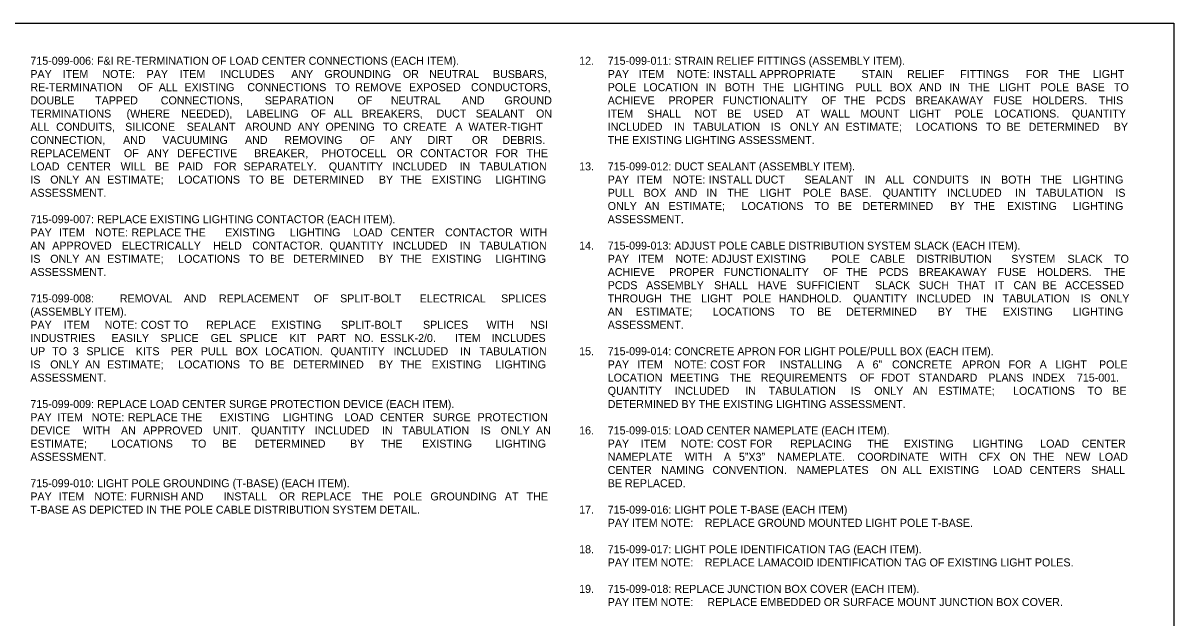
# Model space of a CAD drawing. Extents: x -55 to 2471539, y -90 to 3608906.
# Drawn here: x 543 to 1540, y 445 to 960 of the extents above; entities that cross this region are included whole.
import ezdxf

# ---------------------------------------------------------------- set-up
doc = ezdxf.new("R2010")
doc.units = 0
doc.layers.add('NonPlottingEle_dp', color=7, linetype='Continuous')
doc.layers.add('TextNotes', color=7, linetype='Continuous')

msp = doc.modelspace()

# ---------------------------------------------------------------- linework, layer by layer
at = {"layer": 'NonPlottingEle_dp'}
msp.add_lwpolyline([(0, 0), (0, 960), (1540, 960), (1540, 0)], dxfattribs=at)

# ---------------------------------------------------------------- texts
at = {"layer": 'TextNotes'}
for s, p in [('715-099-006: F&I RE-TERMINATION OF LOAD CENTER CONNECTIONS (EACH ITEM).', (549.7, 923.83)), ('12.', (1024.92, 923.83)), ('715-099-011: STRAIN RELIEF FITTINGS (ASSEMBLY ITEM).', (1049.65, 923.83)), ('PAY ', (549.7, 912.39)), ('ITEM ', (577.74, 912.39)), ('NOTE: ', (612.1, 912.39)), ('PAY ', (650.39, 912.39)), ('ITEM ', (679.08, 912.39)), ('INCLUDES ', (714.25, 912.39)), ('ANY ', (775.58, 912.39)), ('GROUNDING ', (804.34, 912.39)), ('OR ', (872.29, 912.39)), ('NEUTRAL ', (895.07, 912.39)), ('BUSBARS, ', (950.28, 912.39)), ('PAY ', (1049.65, 912.39)), ('ITEM ', (1076.47, 912.39)), ('NOTE:', (1109.6, 912.39)), (' INSTALL APPROPRIATE ', (1138.35, 912.39)), ('STAIN ', (1269.39, 912.39)), ('RELIEF ', (1308.85, 912.39)), ('FITTINGS ', (1354.86, 912.39)), ('FOR ', (1411.77, 912.39)), ('THE ', (1439.97, 912.39)), ('LIGHT ', (1469.78, 912.39)), ('RE-TERMINATION ', (549.7, 900.96)), ('OF ', (643.08, 900.96)), ('ALL ', (660.93, 900.96)), ('EXISTING ', (683.15, 900.96)), ('CONNECTIONS ', (737.56, 900.96)), ('TO ', (813.52, 900.96)), ('REMOVE ', (831.03, 900.96)), ('EXPOSED ', (877.57, 900.96)), ('CONDUCTORS, ', (931.26, 900.96)), ('POLE ', (1049.65, 900.96)), ('LOCATION ', (1080.56, 900.96)), ('IN ', (1134.43, 900.96)), ('BOTH ', (1151.04, 900.96)), ('THE ', (1183.91, 900.96)), ('LIGHTING ', (1210.53, 900.96)), ('PULL ', (1264.1, 900.96)), ('BOX ', (1293.78, 900.96)), ('AND ', (1319.3, 900.96)), ('IN ', (1345.38, 900.96)), ('THE ', (1361.99, 900.96)), ('LIGHT ', (1388.61, 900.96)), ('POLE ', (1424.48, 900.96)), ('BASE ', (1455.39, 900.96)), ('TO ', (1488.08, 900.96)), ('DOUBLE ', (549.7, 889.52)), ('TAPPED ', (605.77, 889.52)), ('CONNECTIONS, ', (662.65, 889.52)), ('SEPARATION ', (752.7, 889.52)), ('OF ', (833, 889.52)), ('NEUTRAL ', (861.91, 889.52)), ('AND ', (923.39, 889.52)), ('GROUND ', (960.17, 889.52)), ('ACHIEVE ', (1049.65, 889.52)), ('PROPER ', (1102.26, 889.52)), ('FUNCTIONALITY ', (1149.23, 889.52)), ('OF ', (1234.77, 889.52)), ('THE ', (1254.12, 889.52)), ('PCDS ', (1281.88, 889.52)), ('BREAKAWAY ', (1316.19, 889.52)), ('FUSE ', (1383.74, 889.52)), ('HOLDERS. ', (1417.5, 889.52)), ('THIS ', (1474.9, 889.52)), ('TERMINATIONS ', (549.7, 878.09)), ('(WHERE ', (633, 878.09)), ('NEEDED), ', (680.31, 878.09)), ('LABELING ', (736.72, 878.09)), ('OF ', (792.62, 878.09)), ('ALL ', (812.36, 878.09)), ('BREAKERS, ', (836.49, 878.09)), ('DUCT ', (901.5, 878.09)), ('SEALANT ', (935.34, 878.09)), ('ON ', (987.58, 878.09)), ('ITEM ', (1049.65, 878.09)), ('SHALL ', (1083.84, 878.09)), ('NOT ', (1124.85, 878.09)), ('BE ', (1153.02, 878.09)), ('USED ', (1175.78, 878.09)), ('AT ', (1212.78, 878.09)), ('WALL ', (1234.12, 878.09)), ('MOUNT ', (1268.41, 878.09)), ('LIGHT ', (1310.87, 878.09)), ('POLE ', (1350.18, 878.09)), ('LOCATIONS. ', (1384.52, 878.09)), ('QUANTITY ', (1451.55, 878.09)), ('ALL ', (549.7, 866.65)), ('CONDUITS, ', (572.05, 866.65)), ('SILICONE ', (631.83, 866.65)), ('SEALANT ', (685.05, 866.65)), ('AROUND ', (735.51, 866.65)), ('ANY ', (781.11, 866.65)), ('OPENING ', (805.22, 866.65)), ('TO ', (854.97, 866.65)), ('CREATE ', (872.61, 866.65)), ('A ', (917.72, 866.65)), ('WATER-TIGHT ', (929.09, 866.65)), ('INCLUDED ', (1049.65, 866.65)), ('IN ', (1107.05, 866.65)), ('TABULATION ', (1123.54, 866.65)), ('IS ', (1190.8, 866.65)), ('ONLY ', (1207.43, 866.65)), ('AN ', (1237.1, 866.65)), ('ESTIMATE; ', (1255.46, 866.65)), ('LOCATIONS ', (1316.43, 866.65)), ('TO ', (1377.19, 866.65)), ('BE ', (1394.94, 866.65)), ('DETERMINED ', (1414.15, 866.65)), ('BY ', (1487.82, 866.65)), ('CONNECTION, ', (549.7, 855.22)), ('AND ', (630.03, 855.22)), ('VACUUMING ', (664.09, 855.22)), ('AND ', (735.55, 855.22)), ('REMOVING ', (769.61, 855.22)), ('OF ', (835.13, 855.22)), ('ANY ', (861.32, 855.22)), ('DIRT ', (893.64, 855.22)), ('OR ', (932.08, 855.22)), ('DEBRIS. ', (958.43, 855.22)), ('THE EXISTING LIGHTING ASSESSMENT.', (1049.65, 855.22)), ('REPLACEMENT ', (549.7, 843.78)), ('OF ', (630.73, 843.78)), ('ANY ', (650.75, 843.78)), ('DEFECTIVE ', (676.9, 843.78)), ('BREAKER, ', (743.47, 843.78)), ('PHOTOCELL ', (801.75, 843.78)), ('OR ', (867.07, 843.78)), ('CONTACTOR ', (887.24, 843.78)), ('FOR ', (952.56, 843.78)), ('THE ', (979.39, 843.78)), ('LOAD ', (549.7, 832.35)), ('CENTER ', (581.37, 832.35)), ('WILL ', (627.9, 832.35)), ('BE ', (657.55, 832.35)), ('PAID ', (677.54, 832.35)), ('FOR ', (708.69, 832.35)), ('SEPARATELY. ', (734.37, 832.35)), ('QUANTITY ', (808.13, 832.35)), ('INCLUDED ', (863.18, 832.35)), ('IN ', (921.36, 832.35)), ('TABULATION ', (938.63, 832.35)), ('13.', (1024.92, 832.35)), ('715-099-012: DUCT SEALANT (ASSEMBLY ITEM).', (1049.65, 832.35)), ('IS ', (549.7, 820.92)), ('ONLY ', (566.92, 820.92)), ('AN ', (597.19, 820.92)), ('ESTIMATE; ', (616.14, 820.92)), ('LOCATIONS ', (677.71, 820.92)), ('TO ', (739.06, 820.92)), ('BE ', (757.41, 820.92)), ('DETERMINED ', (777.21, 820.92)), ('BY ', (851.47, 820.92)), ('THE ', (870.08, 820.92)), ('EXISTING ', (897.18, 820.92)), ('LIGHTING ', (952.43, 820.92)), ('PAY ', (1049.65, 820.92)), ('ITEM ', (1074.62, 820.92)), ('NOTE:', (1105.9, 820.92)), (' INSTALL DUCT ', (1134.65, 820.92)), ('SEALANT ', (1220.03, 820.92)), ('IN ', (1272.07, 820.92)), ('ALL ', (1290.01, 820.92)), ('CONDUITS ', (1313.94, 820.92)), ('IN ', (1372.26, 820.92)), ('BOTH ', (1390.21, 820.92)), ('THE ', (1424.42, 820.92)), ('LIGHTING ', (1452.38, 820.92)), ('ASSESSMENT.', (549.7, 809.48)), ('PULL ', (1049.65, 809.48)), ('BOX ', (1080.74, 809.48)), ('AND ', (1107.67, 809.48)), ('IN ', (1135.17, 809.48)), ('THE ', (1153.18, 809.48)), ('LIGHT ', (1181.21, 809.48)), ('POLE ', (1218.5, 809.48)), ('BASE. ', (1250.83, 809.48)), ('QUANTITY ', (1287.65, 809.48)), ('INCLUDED ', (1343.46, 809.48)), ('IN ', (1402.39, 809.48)), ('TABULATION ', (1420.41, 809.48)), ('IS ', (1489.2, 809.48)), ('ONLY ', (1049.65, 798.05)), ('AN ', (1081.64, 798.05)), ('ESTIMATE; ', (1102.31, 798.05)), ('LOCATIONS ', (1165.6, 798.05)), ('TO ', (1228.68, 798.05)), ('BE ', (1248.75, 798.05)), ('DETERMINED ', (1270.27, 798.05)), ('BY ', (1346.26, 798.05)), ('THE ', (1366.59, 798.05)), ('EXISTING ', (1395.4, 798.05)), ('LIGHTING ', (1452.38, 798.05)), ('715-099-007: REPLACE EXISTING LIGHTING CONTACTOR (EACH ITEM).', (549.7, 786.61)), ('ASSESSMENT.', (1049.65, 786.61)), ('PAY ', (549.7, 775.18)), ('ITEM ', (574.65, 775.18)), ('NOTE:', (605.91, 775.18)), (' REPLACE THE ', (634.66, 775.18)), ('EXISTING ', (718.38, 775.18)), ('LIGHTING ', (774.46, 775.18)), ('LOAD ', (829.35, 775.18)), ('CENTER ', (861.68, 775.18)), ('CONTACTOR ', (908.87, 775.18)), ('WITH ', (973.69, 775.18)), ('AN ', (549.7, 763.74)), ('APPROVED ', (568.66, 763.74)), ('ELECTRICALLY ', (628.89, 763.74)), ('HELD ', (708.04, 763.74)), ('CONTACTOR. ', (741.94, 763.74)), ('QUANTITY ', (808.65, 763.74)), ('INCLUDED ', (863.54, 763.74)), ('IN ', (921.54, 763.74)), ('TABULATION ', (938.63, 763.74)), ('14.', (1024.92, 763.74)), ('715-099-013: ADJUST POLE CABLE DISTRIBUTION SYSTEM SLACK (EACH ITEM).', (1049.65, 763.74)), ('IS ', (549.7, 752.31)), ('ONLY ', (566.92, 752.31)), ('AN ', (597.19, 752.31)), ('ESTIMATE; ', (616.14, 752.31)), ('LOCATIONS ', (677.71, 752.31)), ('TO ', (739.06, 752.31)), ('BE ', (757.41, 752.31)), ('DETERMINED ', (777.21, 752.31)), ('BY ', (851.47, 752.31)), ('THE ', (870.08, 752.31)), ('EXISTING ', (897.18, 752.31)), ('LIGHTING ', (952.43, 752.31)), ('PAY ', (1049.65, 752.31)), ('ITEM ', (1075.83, 752.31)), ('NOTE:', (1108.32, 752.31)), (' ADJUST EXISTING ', (1137.07, 752.31)), ('POLE ', (1243.33, 752.31)), ('CABLE ', (1276.79, 752.31)), ('DISTRIBUTION ', (1317.01, 752.31)), ('SYSTEM ', (1399.13, 752.31)), ('SLACK ', (1447.85, 752.31)), ('TO ', (1488.08, 752.31)), ('ASSESSMENT.', (549.7, 740.87)), ('ACHIEVE ', (1049.65, 740.87)), ('PROPER ', (1102.75, 740.87)), ('FUNCTIONALITY ', (1150.22, 740.87)), ('OF ', (1236.24, 740.87)), ('THE ', (1256.09, 740.87)), ('PCDS ', (1284.34, 740.87)), ('BREAKAWAY ', (1319.14, 740.87)), ('FUSE ', (1387.19, 740.87)), ('HOLDERS. ', (1421.44, 740.87)), ('THE ', (1479.34, 740.87)), ('PCDS ', (1049.65, 729.44)), ('ASSEMBLY ', (1082.95, 729.44)), ('SHALL ', (1141.8, 729.44)), ('HAVE ', (1179.52, 729.44)), ('SUFFICIENT ', (1213.08, 729.44)), ('SLACK ', (1281.14, 729.44)), ('SUCH ', (1318.96, 729.44)), ('THAT ', (1352.48, 729.44)), ('IT ', (1384.84, 729.44)), ('CAN ', (1401.03, 729.44)), ('BE ', (1426.14, 729.44)), ('ACCESSED ', (1445.6, 729.44)), ('715-099-008: ', (549.7, 718.01)), ('REMOVAL ', (627.22, 718.01)), ('AND ', (682.58, 718.01)), ('REPLACEMENT ', (713.02, 718.01)), ('OF ', (795.16, 718.01)), ('SPLIT-BOLT ', (817.95, 718.01)), ('ELECTRICAL ', (886.82, 718.01)), ('SPLICES ', (957.38, 718.01)), ('THROUGH ', (1049.65, 718.01)), ('THE ', (1103.55, 718.01)), ('LIGHT ', (1130.43, 718.01)), ('POLE ', (1166.57, 718.01)), ('HANDHOLD. ', (1197.74, 718.01)), ('QUANTITY ', (1262.2, 718.01)), ('INCLUDED ', (1316.86, 718.01)), ('IN ', (1374.64, 718.01)), ('TABULATION ', (1391.51, 718.01)), ('IS ', (1459.15, 718.01)), ('ONLY ', (1476.16, 718.01)), ('(ASSEMBLY ITEM).', (549.7, 706.57)), ('AN ', (1049.65, 706.57)), ('ESTIMATE; ', (1073.88, 706.57)), ('LOCATIONS ', (1140.72, 706.57)), ('TO ', (1207.35, 706.57)), ('BE ', (1230.98, 706.57)), ('DETERMINED ', (1256.05, 706.57)), ('BY ', (1335.59, 706.57)), ('THE ', (1359.48, 706.57)), ('EXISTING ', (1391.85, 706.57)), ('LIGHTING ', (1452.38, 706.57)), ('PAY ', (549.7, 695.14)), ('ITEM ', (578.71, 695.14)), ('NOTE:', (614.04, 695.14)), (' COST TO ', (642.79, 695.14)), ('REPLACE ', (701.88, 695.14)), ('EXISTING ', (758.59, 695.14)), ('SPLIT-BOLT ', (818.75, 695.14)), ('SPLICES ', (889.71, 695.14)), ('WITH ', (944.7, 695.14)), ('NSI ', (982.39, 695.14)), ('ASSESSMENT.', (1049.65, 695.14)), ('INDUSTRIES ', (549.7, 683.7)), ('EASILY ', (620.06, 683.7)), ('SPLICE ', (662.4, 683.7)), ('GEL ', (705.81, 683.7)), ('SPLICE ', (730.78, 683.7)), ('KIT ', (774.19, 683.7)), ('PART ', (798.14, 683.7)), ('NO. ', (830.48, 683.7)), ('ESSLK-2/0. ', (852.45, 683.7)), ('ITEM ', (917.5, 683.7)), ('INCLUDES ', (949.08, 683.7)), ('UP ', (549.7, 672.27)), ('TO ', (568.55, 672.27)), ('3 ', (586.58, 672.27)), ('SPLICE ', (598.22, 672.27)), ('KITS ', (640.97, 672.27)), ('PER ', (671.27, 672.27)), ('PULL ', (697.35, 672.27)), ('BOX ', (727.19, 672.27)), ('LOCATION. ', (752.87, 672.27)), ('QUANTITY ', (809.62, 672.27)), ('INCLUDED ', (864.18, 672.27)), ('IN ', (921.86, 672.27)), ('TABULATION ', (938.63, 672.27)), ('15.', (1024.92, 672.27)), ('715-099-014: CONCRETE APRON FOR LIGHT POLE/PULL BOX (EACH ITEM).', (1049.65, 672.27)), ('IS ', (549.7, 660.83)), ('ONLY ', (566.92, 660.83)), ('AN ', (597.19, 660.83)), ('ESTIMATE; ', (616.14, 660.83)), ('LOCATIONS ', (677.71, 660.83)), ('TO ', (739.06, 660.83)), ('BE ', (757.41, 660.83)), ('DETERMINED ', (777.21, 660.83)), ('BY ', (851.47, 660.83)), ('THE ', (870.08, 660.83)), ('EXISTING ', (897.18, 660.83)), ('LIGHTING ', (952.43, 660.83)), ('PAY ', (1049.65, 660.83)), ('ITEM ', (1075.2, 660.83)), ('NOTE:', (1107.07, 660.83)), (' COST FOR ', (1135.81, 660.83)), ('INSTALLING ', (1198.59, 660.83)), ('A ', (1265.47, 660.83)), ('6” ', (1279, 660.83)), ('CONCRETE ', (1295.89, 660.83)), ('APRON ', (1356.48, 660.83)), ('FOR ', (1396.78, 660.83)), ('A ', (1423.72, 660.83)), ('LIGHT ', (1437.25, 660.83)), ('POLE ', (1475.04, 660.83)), ('ASSESSMENT.', (549.7, 649.4)), ('LOCATION ', (1049.65, 649.4)), ('MEETING ', (1103.84, 649.4)), ('THE ', (1155.2, 649.4)), ('REQUIREMENTS ', (1182.14, 649.4)), ('OF ', (1267.79, 649.4)), ('FDOT ', (1286.32, 649.4)), ('STANDARD ', (1318.77, 649.4)), ('PLANS ', (1379.26, 649.4)), ('INDEX ', (1417.35, 649.4)), ('715-001. ', (1455.91, 649.4)), ('QUANTITY ', (1049.65, 637.96)), ('INCLUDED ', (1107.67, 637.96)), ('IN ', (1168.81, 637.96)), ('TABULATION ', (1189.04, 637.96)), ('IS ', (1260.04, 637.96)), ('ONLY ', (1280.41, 637.96)), ('AN ', (1313.83, 637.96)), ('ESTIMATE; ', (1335.92, 637.96)), ('LOCATIONS ', (1400.64, 637.96)), ('TO ', (1465.14, 637.96)), ('BE ', (1486.63, 637.96)), ('715-099-009: REPLACE LOAD CENTER SURGE PROTECTION DEVICE (EACH ITEM).', (549.7, 626.53)), ('DETERMINED BY THE EXISTING LIGHTING ASSESSMENT.', (1049.65, 626.53)), ('PAY ', (549.7, 615.09)), ('ITEM ', (573.11, 615.09)), ('NOTE:', (602.83, 615.09)), (' REPLACE THE ', (631.58, 615.09)), ('EXISTING ', (713.76, 615.09)), ('LIGHTING ', (768.31, 615.09)), ('LOAD ', (821.67, 615.09)), ('CENTER ', (852.46, 615.09)), ('SURGE ', (898.1, 615.09)), ('PROTECTION ', (937, 615.09)), ('DEVICE ', (549.7, 603.66)), ('WITH ', (595.15, 603.66)), ('AN ', (628.17, 603.66)), ('APPROVED ', (647.36, 603.66)), ('UNIT. ', (707.81, 603.66)), ('QUANTITY ', (740.82, 603.66)), ('INCLUDED ', (795.93, 603.66)), ('IN ', (854.16, 603.66)), ('TABULATION ', (871.48, 603.66)), ('IS ', (939.57, 603.66)), ('ONLY ', (957.03, 603.66)), ('AN ', (987.53, 603.66)), ('16.', (1024.92, 603.66)), ('715-099-015: LOAD CENTER NAMEPLATE (EACH ITEM).', (1049.65, 603.66)), ('ESTIMATE; ', (549.7, 592.23)), ('LOCATIONS ', (619.57, 592.23)), ('TO ', (689.23, 592.23)), ('BE ', (715.88, 592.23)), ('DETERMINED ', (743.99, 592.23)), ('BY ', (826.56, 592.23)), ('THE ', (853.47, 592.23)), ('EXISTING ', (888.87, 592.23)), ('LIGHTING ', (952.43, 592.23)), ('PAY ', (1049.65, 592.23)), ('ITEM ', (1078.19, 592.23)), ('NOTE:', (1113.05, 592.23)), (' COST FOR ', (1141.8, 592.23)), ('REPLACING ', (1207.57, 592.23)), ('THE ', (1274.45, 592.23)), ('EXISTING ', (1305.98, 592.23)), ('LIGHTING ', (1365.67, 592.23)), ('LOAD ', (1424.16, 592.23)), ('CENTER ', (1460.09, 592.23)), ('ASSESSMENT.', (549.7, 580.79)), ('NAMEPLATE ', (1049.65, 580.79)), ('WITH ', (1116.36, 580.79)), ('A ', (1150.17, 580.79)), ('5”X3” ', (1163.28, 580.79)), ('NAMEPLATE. ', (1196.44, 580.79)), ('COORDINATE ', (1265.87, 580.79)), ('WITH ', (1337.24, 580.79)), ('CFX ', (1371.06, 580.79)), ('ON ', (1397.91, 580.79)), ('THE ', (1417.85, 580.79)), ('NEW ', (1445.97, 580.79)), ('LOAD ', (1474.94, 580.79)), ('CENTER ', (1049.65, 569.36)), ('NAMING ', (1096.05, 569.36)), ('CONVENTION. ', (1140.41, 569.36)), ('NAMEPLATES ', (1213.26, 569.36)), ('ON ', (1286.01, 569.36)), ('ALL ', (1304.97, 569.36)), ('EXISTING ', (1328.1, 569.36)), ('LOAD ', (1383.41, 569.36)), ('CENTERS ', (1414.96, 569.36)), ('SHALL ', (1468.36, 569.36)), ('715-099-010: LIGHT POLE GROUNDING (T-BASE) (EACH ITEM).', (549.7, 557.92)), ('BE REPLACED.', (1049.65, 557.92)), ('PAY ', (549.7, 546.49)), ('ITEM ', (574.25, 546.49)), ('NOTE:', (605.11, 546.49)), (' FURNISH AND ', (633.86, 546.49)), ('INSTALL ', (717.03, 546.49)), ('OR ', (765.21, 546.49)), ('REPLACE ', (784.49, 546.49)), ('THE ', (836.74, 546.49)), ('POLE ', (864.27, 546.49)), ('GROUNDING ', (896.1, 546.49)), ('AT ', (960.55, 546.49)), ('THE ', (979.39, 546.49)), ('T-BASE AS DEPICTED IN THE POLE CABLE DISTRIBUTION SYSTEM DETAIL.', (549.7, 535.05)), ('17.', (1024.92, 535.05)), ('715-099-016: LIGHT POLE T-BASE (EACH ITEM)', (1049.65, 535.05)), ('PAY ITEM NOTE:', (1049.65, 523.62)), (' REPLACE GROUND MOUNTED LIGHT POLE T-BASE.', (1131.18, 523.62)), ('18.', (1024.92, 500.75)), ('715-099-017: LIGHT POLE IDENTIFICATION TAG (EACH ITEM).', (1049.65, 500.75)), ('PAY ITEM NOTE:', (1049.65, 489.32)), (' REPLACE LAMACOID IDENTIFICATION TAG OF EXISTING LIGHT POLES.', (1131.18, 489.32)), ('19.', (1024.92, 466.45)), ('715-099-018: REPLACE JUNCTION BOX COVER (EACH ITEM).', (1049.65, 466.45)), ('PAY ITEM NOTE: ', (1049.65, 455.01)), ('REPLACE EMBEDDED OR SURFACE MOUNT JUNCTION BOX COVER.', (1135.9, 455.01))]:
    msp.add_text(s, height=6.93, dxfattribs=at).set_placement(p)

doc.saveas('drawing.dxf')
